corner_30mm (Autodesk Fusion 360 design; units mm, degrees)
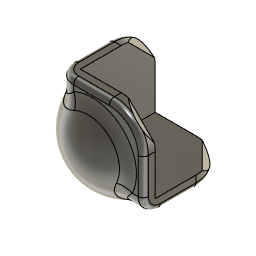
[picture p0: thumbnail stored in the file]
sketch "Sketch1" plane through (0, 0, 0) normal (0, 0, 1) x axis (1, 0, 0)
  line L1 (102, 0) -> (0, 0)
  line L2 (102, 72) -> (102, 0)
  line L3 (0, 72) -> (102, 72)
  line L4 (0, 0) -> (0, 72)
  point P1 (0, 0)
  point P2 (0, 0)
  horizontal L1
  vertical L2
  horizontal L3
  vertical L4
  coincident P1 P2
place_component sketch "Sketch1"
extrude "Extrude1" new body sketch "Sketch1" along normal blind 50
sketch "Sketch2" plane through (0, 0, 0) normal (1, 0, 0) x axis (0, 1, 0)
  line L1 (0, -16.5) -> (0, 16.7321)
  circle C1 centre (0, 0) radius 15
  point P1 (0, 0)
  point P2 (0, 0)
  coincident P1 P2
  vertical L1
  coincident P1 L1
  dimension "d3" diameter C1 = 30
revolve "Revolve1" sketch "Sketch2" AlongAngle 360
move "Move1"
combine "Combine1"
sketch "Sketch3" plane through (0, 0, 0) normal (0, -1, 0) x axis (1, 0, 0)
  line L1 (102, 0) -> (0, 0)
  line L2 (102, 50) -> (102, 0)
  line L3 (0, 50) -> (102, 50)
  line L4 (0, 0) -> (0, 50)
  line L5 (22, 0) -> (0, 0)
  line L6 (22, 22) -> (22, 0)
  line L7 (0, 22) -> (22, 22)
  line L8 (0, 0) -> (0, 22)
  point P1 (0, 0)
  point P6 (0, 0)
  point P7 (22, 0)
  point P9 (0, 22)
  horizontal L5
  vertical L6
  horizontal L7
  vertical L8
  coincident P1 P6
  dimension "d5" distance P6 P7 = 22
  dimension "d6" distance P6 P9 = 22
extrude "Extrude1" add sketch "Sketch3" profile of L1 L4 L5 L6 L7 L8 along normal blind 3.5
sketch "Sketch5" plane through (0, 0, 0) normal (-1, 0, 0) x axis (0, -1, 0)
  line L1 (3.5, 22) -> (3.5, 15.1086)
  line L2 (0, 22) -> (3.5, 22)
  line L3 (0, 18.2694) -> (0, 22)
  line L4 (-22, 22) -> (3.5, 22)
  line L5 (-22, 0) -> (-22, 22)
  line L6 (3.5, 0) -> (-22, 0)
  line L7 (3.5, 22) -> (3.5, 0)
  arc A1 centre (-7, 7) radius 13.2665 clockwise from (0, 18.2694) to (3.5, 15.1086)
  point P5 (3.5, 22)
  point P7 (3.5, 22)
  point P1 (0, 0)
  horizontal L4
  vertical L5
  horizontal L6
  vertical L7
  coincident P5 P7
  coincident P1 L6
  dimension "d13" distance L3 L5 = 22
extrude "Extrude3" add sketch "Sketch5" profile of A1 L3 L4 L5 L6 L7 along normal blind 3.5
sketch "Sketch6" plane through (0, 0, 0) normal (0, 0, -1) x axis (1, 0, 0)
  line L1 (22, 0) -> (18.2694, 0)
  line L2 (22, 3.5) -> (22, 0)
  line L3 (15.1086, 3.5) -> (22, 3.5)
  line L4 (-3.5, 3.5) -> (22, 3.5)
  line L5 (-3.5, -22) -> (-3.5, 3.5)
  line L6 (22, -22) -> (-3.5, -22)
  line L7 (22, 3.5) -> (22, -22)
  arc A1 centre (7, -7) radius 13.2665 clockwise from (15.1086, 3.5) to (18.2694, 0)
  point P6 (22, 3.5)
  point P7 (22, 3.5)
  point P11 (-3.5, -22)
  horizontal L4
  vertical L5
  horizontal L6
  vertical L7
  coincident P6 P7
  coincident L5 P11
  coincident L6 P11
extrude "Extrude4" add sketch "Sketch6" along normal blind 3.5
delete_face "DeleteFace1"
fillet "Fillet1" radius 10
fillet "Fillet2" radius 5
fillet "Fillet3" radius 6
work_plane "WorkPlane1"
work_plane "WorkPlane2" AlongDistance 8
split "Split1"
remove_body "RemoveBody1"
remove_body "RemoveBody2"
remove_body "RemoveBody3"
fillet "Fillet4" radius 1.5
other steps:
create_component "CreateComponent1" sketch "Sketch1"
